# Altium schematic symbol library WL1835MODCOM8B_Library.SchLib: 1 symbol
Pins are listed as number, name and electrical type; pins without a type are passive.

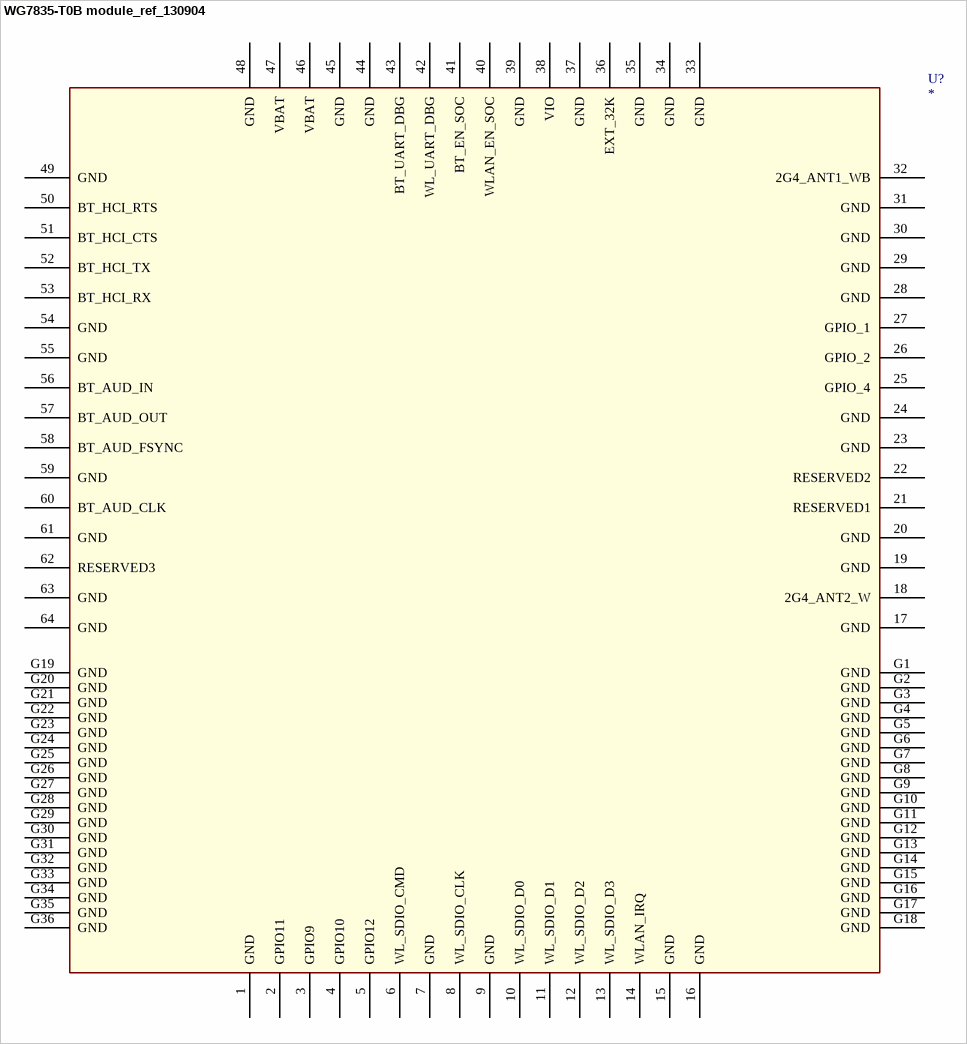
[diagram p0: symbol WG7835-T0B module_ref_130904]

## WG7835-T0B module_ref_130904
designator U?
footprint E-13.4X13.3-N100_0.75-TOP
pins: 1 GND (power), 2 GPIO11, 3 GPIO9, 4 GPIO10, 5 GPIO12, 6 WL_SDIO_CMD, 7 GND (power), 8 WL_SDIO_CLK, 9 GND (power), 10 WL_SDIO_D0, 11 WL_SDIO_D1, 12 WL_SDIO_D2, 13 WL_SDIO_D3, 14 WLAN_IRQ, 15 GND (power), 16 GND (power), 17 GND (power), 18 2G4_ANT2_W, 19 GND (power), 20 GND (power), 21 RESERVED1, 22 RESERVED2, 23 GND (power), 24 GND (power), 25 GPIO_4, 26 GPIO_2, 27 GPIO_1, 28 GND (power), 29 GND (power), 30 GND (power), 31 GND (power), 32 2G4_ANT1_WB, 33 GND (power), 34 GND (power), 35 GND (power), 36 EXT_32K, 37 GND (power), 38 VIO (power), 39 GND (power), 40 WLAN_EN_SOC, 41 BT_EN_SOC, 42 WL_UART_DBG, 43 BT_UART_DBG, 44 GND (power), 45 GND (power), 46 VBAT (power), 47 VBAT (power), 48 GND (power), 49 GND (power), 50 BT_HCI_RTS, 51 BT_HCI_CTS, 52 BT_HCI_TX, 53 BT_HCI_RX, 54 GND (power), 55 GND (power), 56 BT_AUD_IN, 57 BT_AUD_OUT, 58 BT_AUD_FSYNC, 59 GND (power), 60 BT_AUD_CLK, 61 GND (power), 62 RESERVED3, 63 GND (power), 64 GND (power), G1 GND (power), G2 GND (power), G3 GND (power), G4 GND (power), G5 GND (power), G6 GND (power), G7 GND (power), G8 GND (power), G9 GND (power), G10 GND (power), G11 GND (power), G12 GND (power), G13 GND (power), G14 GND (power), G15 GND (power), G16 GND (power), G17 GND (power), G18 GND (power), G19 GND (power), G20 GND (power), G21 GND (power), G22 GND (power), G23 GND (power), G24 GND (power), G25 GND (power), G26 GND (power), G27 GND (power), G28 GND (power), G29 GND (power), G30 GND (power), G31 GND (power), G32 GND (power), G33 GND (power), G34 GND (power), G35 GND (power), G36 GND (power)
